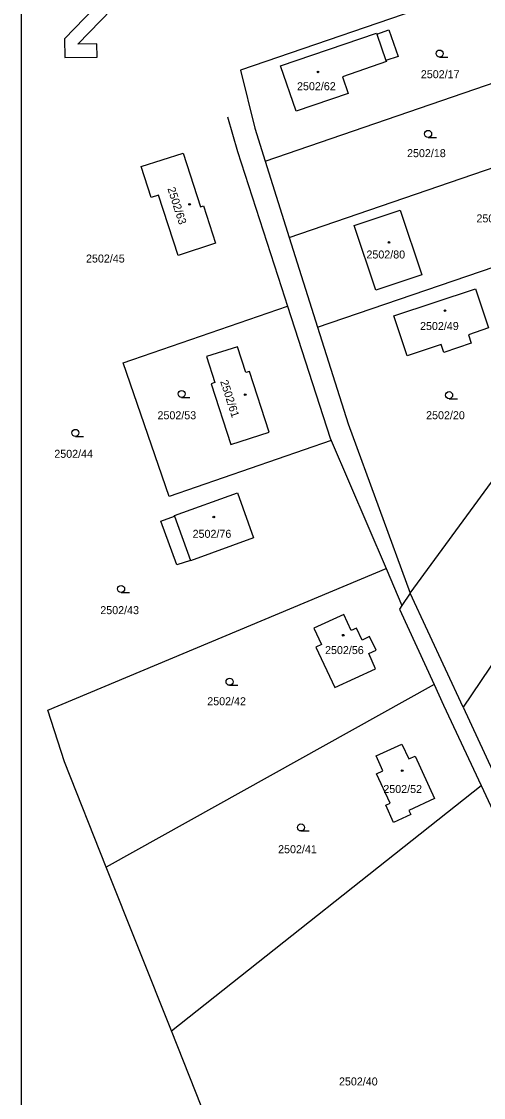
# Model space of a CAD drawing. Extents: x -558358 to -557517, y -1073785 to -1073189.
# Drawn here: x -558357.5 to -558259.4, y -1073555.9 to -1073327.3 of the extents above; entities that cross this region are included whole.
import ezdxf

# ---------------------------------------------------------------- set-up
doc = ezdxf.new("R2010")
doc.units = 0
for name, color, linetype in [('Hranice parcel', 7, 'Continuous'), ('Parcelní čísla', 7, 'Continuous'), ('Rozpiska_pole_1', 7, 'Continuous'), ('Vnitřní kresba', 7, 'Continuous'), ('Značky budov', 7, 'Continuous'), ('Značky kultur', 7, 'Continuous')]:
    doc.layers.add(name, color=color, linetype=linetype)

msp = doc.modelspace()

# ---------------------------------------------------------------- linework, layer by layer
at = {"layer": 'Hranice parcel'}
for p, q in [((-558245.27, -1073315.03), (-558311.02, -1073337.58)), ((-558305.76, -1073356.92), (-558240.15, -1073334.41)), ((-558300.65, -1073373.14), (-558235.73, -1073350.87)), ((-558305.76, -1073356.92), (-558300.65, -1073373.14)), ((-558294.64, -1073392.22), (-558230.35, -1073370.17)), ((-558300.65, -1073373.14), (-558294.64, -1073392.22)), ((-558302.31, -1073383.75), (-558301.02, -1073387.75)), ((-558335.97, -1073399.79), (-558301.02, -1073387.75)), ((-558294.64, -1073392.22), (-558288.18, -1073412.71)), ((-558326.19, -1073428.15), (-558335.97, -1073399.79)), ((-558288.18, -1073412.71), (-558274.97, -1073448.74)), ((-558291.74, -1073416.28), (-558326.19, -1073428.15)), ((-558291.74, -1073416.28), (-558280.07, -1073443.5)), ((-558274.97, -1073448.74), (-558257.7, -1073425.14)), ((-558351.92, -1073473.58), (-558280.07, -1073443.5)), ((-558280.07, -1073443.5), (-558276.72, -1073451.31)), ((-558274.97, -1073448.74), (-558276.72, -1073451.31)), ((-558263.73, -1073472.95), (-558274.97, -1073448.74)), ((-558269.87, -1073468.15), (-558339.52, -1073506.95)), ((-558325.69, -1073541.72), (-558259.89, -1073489.61)), ((-558325.69, -1073541.72), (-558339.52, -1073506.95)), ((-558314.35, -1073570.26), (-558325.69, -1073541.72))]:
    msp.add_line(p, q, dxfattribs=at)
for points in [[(-558302.49, -1073336.69), (-558282.13, -1073329.71), (-558282.06, -1073329.92), (-558279.49, -1073329.04), (-558277.55, -1073334.7), (-558280.12, -1073335.56), (-558280.04, -1073335.79), (-558289.36, -1073338.99), (-558288.15, -1073342.54), (-558299.21, -1073346.34), (-558302.49, -1073336.69)], [(-558311.02, -1073337.58), (-558307.96, -1073349.92), (-558305.76, -1073356.92)], [(-558313.78, -1073347.52), (-558311.65, -1073354.86), (-558302.31, -1073383.75)], [(-558329.99, -1073364.63), (-558332.12, -1073358.09), (-558323.21, -1073355.2), (-558319.51, -1073366.6), (-558318.91, -1073366.43), (-558316.33, -1073374.39), (-558324.28, -1073376.97), (-558328.43, -1073364.14), (-558329.99, -1073364.63)], [(-558282.25, -1073384.34), (-558286.86, -1073370.59), (-558277.14, -1073367.32), (-558272.5, -1073381.07), (-558282.25, -1073384.34)], [(-558278.42, -1073389.81), (-558261.13, -1073384.05), (-558258.31, -1073392.37), (-558262.58, -1073393.82), (-558262, -1073395.6), (-558267.81, -1073397.55), (-558268.37, -1073395.87), (-558275.59, -1073398.26), (-558278.42, -1073389.81)], [(-558301.02, -1073387.75), (-558291.95, -1073415.8), (-558291.74, -1073416.28)], [(-558309.9, -1073401.85), (-558311.67, -1073396.36), (-558318.22, -1073398.44), (-558316.44, -1073403.96), (-558317.23, -1073404.23), (-558313.09, -1073417.12), (-558304.96, -1073414.53), (-558309.1, -1073401.61), (-558309.9, -1073401.85)], [(-558321.61, -1073441.85), (-558321.65, -1073441.75), (-558324.57, -1073442.7), (-558327.97, -1073433.39), (-558325.04, -1073432.33), (-558325.07, -1073432.22), (-558311.66, -1073427.42), (-558308.26, -1073436.97), (-558321.61, -1073441.85)], [(-558252.58, -1073492.61), (-558249.44, -1073487.92), (-558239.75, -1073494.46), (-558236.97, -1073490.34), (-558223.28, -1073470.09), (-558220.49, -1073465.96), (-558246.94, -1073448.09), (-558263.73, -1073472.95)], [(-558287.54, -1073456.66), (-558289.07, -1073453.28), (-558295.45, -1073456.18), (-558293.85, -1073459.61), (-558295.04, -1073460.19), (-558290.99, -1073468.78), (-558282.34, -1073464.77), (-558283.75, -1073461.57), (-558282.21, -1073460.84), (-558283.59, -1073457.95), (-558285.18, -1073458.67), (-558286.36, -1073456.15), (-558287.54, -1073456.66)], [(-558276.72, -1073451.31), (-558277.28, -1073452.14), (-558269.87, -1073468.15)], [(-558269.87, -1073468.15), (-558267.87, -1073472.49), (-558259.89, -1073489.61)], [(-558339.52, -1073506.95), (-558348.44, -1073484.55), (-558351.92, -1073473.58)], [(-558263.73, -1073472.95), (-558257.48, -1073486.4), (-558252.9, -1073491.92), (-558252.58, -1073492.61)], [(-558280.17, -1073493.77), (-558279.26, -1073493.36), (-558282.12, -1073487.08), (-558280.77, -1073486.48), (-558282.2, -1073483.29), (-558276.72, -1073480.79), (-558275.28, -1073483.95), (-558273.92, -1073483.36), (-558269.81, -1073492.38), (-558275.26, -1073494.86), (-558274.85, -1073495.76), (-558278.51, -1073497.42), (-558280.17, -1073493.77)], [(-558259.89, -1073489.61), (-558244.04, -1073523.6), (-558239.03, -1073535.96)]]:
    msp.add_lwpolyline(points, dxfattribs=at)
at = {"layer": 'Rozpiska_pole_1'}
for p, q in [((-558357.53, -1073784.09), (-558357.53, -1073190.09)), ((-558280.86, -1073260.92), (-558348.4, -1073330.92)), ((-558345.54, -1073332.05), (-558278.82, -1073262.89)), ((-558348.4, -1073330.92), (-558348.32, -1073334.93)), ((-558341.53, -1073331.97), (-558345.54, -1073332.05)), ((-558341.48, -1073334.81), (-558341.53, -1073331.97)), ((-558348.32, -1073334.93), (-558341.48, -1073334.81))]:
    msp.add_line(p, q, dxfattribs=at)
at = {"layer": 'Vnitřní kresba'}
for p, q in [((-558282.06, -1073329.92), (-558280.12, -1073335.56)), ((-558325.04, -1073432.33), (-558321.65, -1073441.75))]:
    msp.add_line(p, q, dxfattribs=at)
at = {"layer": 'Značky budov'}
for centre in [(-558294.55, -1073337.97), (-558321.85, -1073366.12), (-558279.47, -1073374.21), (-558267.57, -1073388.69), (-558310.02, -1073406.56), (-558316.7, -1073432.55), (-558289.2, -1073457.65), (-558276.67, -1073486.42)]:
    msp.add_circle(centre, 0.175, dxfattribs=at)
at = {"layer": 'Značky kultur'}
for p, q in [((-558268.73, -1073334.82), (-558266.98, -1073334.82)), ((-558271.17, -1073351.89), (-558269.42, -1073351.89)), ((-558323.52, -1073407.14), (-558321.77, -1073407.14)), ((-558266.71, -1073407.4), (-558264.96, -1073407.4)), ((-558346.09, -1073415.41), (-558344.34, -1073415.41)), ((-558336.38, -1073448.57), (-558334.63, -1073448.57)), ((-558313.35, -1073468.3), (-558311.6, -1073468.3)), ((-558298.17, -1073499.24), (-558296.42, -1073499.24))]:
    msp.add_line(p, q, dxfattribs=at)
for centre in [(-558268.73, -1073334.07), (-558271.17, -1073351.14), (-558323.52, -1073406.39), (-558266.71, -1073406.65), (-558346.09, -1073414.66), (-558336.38, -1073447.82), (-558313.35, -1073467.55), (-558298.17, -1073498.49)]:
    msp.add_circle(centre, 0.75, dxfattribs=at)

# ---------------------------------------------------------------- texts
at = {"layer": 'Parcelní čísla'}
for s, p in [('2502/17', (-558272.71, -1073339.31)), ('2502/62', (-558299.01, -1073341.86)), ('2502/18', (-558275.64, -1073356.08)), ('2502/19', (-558260.9, -1073369.94)), ('2502/80', (-558284.27, -1073377.61)), ('2502/45', (-558343.83, -1073378.47)), ('2502/49', (-558272.88, -1073392.81)), ('2502/53', (-558328.65, -1073411.77)), ('2502/20', (-558271.59, -1073411.76)), ('2502/44', (-558350.57, -1073419.96)), ('2502/76', (-558321.19, -1073436.96)), ('2502/43', (-558340.8, -1073453.18)), ('2502/56', (-558293.06, -1073461.66)), ('2502/42', (-558318.08, -1073472.53)), ('2502/52', (-558280.68, -1073491.18)), ('2502/41', (-558303.03, -1073503.97)), ('2502/40', (-558290.1, -1073553.31))]:
    msp.add_text(s, height=1.7, dxfattribs=at).set_placement(p)
for s, p in [('2502/63', (-558326.57, -1073362.74)), ('2502/61', (-558315.36, -1073403.73))]:
    msp.add_text(s, height=1.7, rotation=288, dxfattribs=at).set_placement(p)

doc.saveas('drawing.dxf')
